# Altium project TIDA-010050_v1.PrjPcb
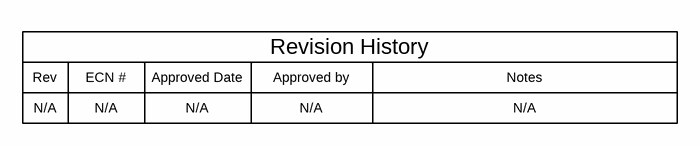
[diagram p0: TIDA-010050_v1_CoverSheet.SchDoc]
CopyrightYear: 2018; PCB_Layout: Aki Li; PCB_Rev: E1; PRJ_Customer: Public Release; PRJ_Engineer: Aki Li, Milen Stefanov; PRJ_Number: TIDA-010050; PRJ_Title: Ultra Low Power Flow Measurement Reference Design Using RF Wireless MCU; SCH_Rev: E1; TechSupport: http://www.ti.com/support; TID: TIDA-010050
3 sheets, 59 parts. Net scope: global (net labels, ports and power ports of the same name join across sheets).
Board file: TIDA-010050_v1.PcbDoc
Sheets:
  TIDA-010050_v1_CoverSheet.SchDoc
  TIDA-010050_v1_Hardware.SchDoc
  TIDA-010050_v1.SchDoc

## Sheet TIDA-010050_v1_CoverSheet.SchDoc
size 431 x 279 mm; Date: Not shown in title block; ApprovedBy: Not shown in title block; CheckedBy: Not shown in title block; Author: Not shown in title block; CompanyName: Not shown in title block; Engineer: Not shown in title block; Organization: Not shown in title block; Address1: Not shown in title block; Address2: Not shown in title block; Address3: Not shown in title block; Address4: Not shown in title block; DocumentNumber: 1; Revision: Use project parameter SCH_Rev; SheetNumber: 1; SheetTotal: 3; PageSetup: Record=PageOptions¦CenterHorizontal=True¦CenterVertical=True¦PrintScale=1.00¦XCorrection=1.00¦YCorrection=1.00¦PrintKind=0¦BorderSize=5000000¦LeftOffset=0¦BottomOffset=0¦Orientation=2¦PaperLength=1000¦PaperWidth=1000¦Scale=100¦PaperSource=15¦PrintQuality=600¦MediaType=1¦DitherType=10¦PaperKind=Letter¦PrintScaleMode=1

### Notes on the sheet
- Rev
- N/A
- ECN #
- Approved Date
- Approved by
- Revision History
- Notes

## Sheet TIDA-010050_v1_Hardware.SchDoc
size 431 x 279 mm; Date: Not shown in title block; ApprovedBy: Not shown in title block; CheckedBy: Not shown in title block; Author: Not shown in title block; CompanyName: Not shown in title block; Engineer: Not shown in title block; Organization: Not shown in title block; Address1: Not shown in title block; Address2: Not shown in title block; Address3: Not shown in title block; Address4: Not shown in title block; DocumentNumber: 3; Revision: Use project parameter SCH_Rev; SheetNumber: 3; SheetTotal: 3; PageSetup: Record=PageOptions¦CenterHorizontal=True¦CenterVertical=True¦PrintScale=1.00¦XCorrection=1.00¦YCorrection=1.00¦PrintKind=0¦BorderSize=5000000¦LeftOffset=0¦BottomOffset=0¦Orientation=2¦PaperLength=1000¦PaperWidth=1000¦Scale=100¦PaperSource=15¦PrintQuality=600¦MediaType=1¦DitherType=10¦PaperKind=Letter¦PrintScaleMode=1
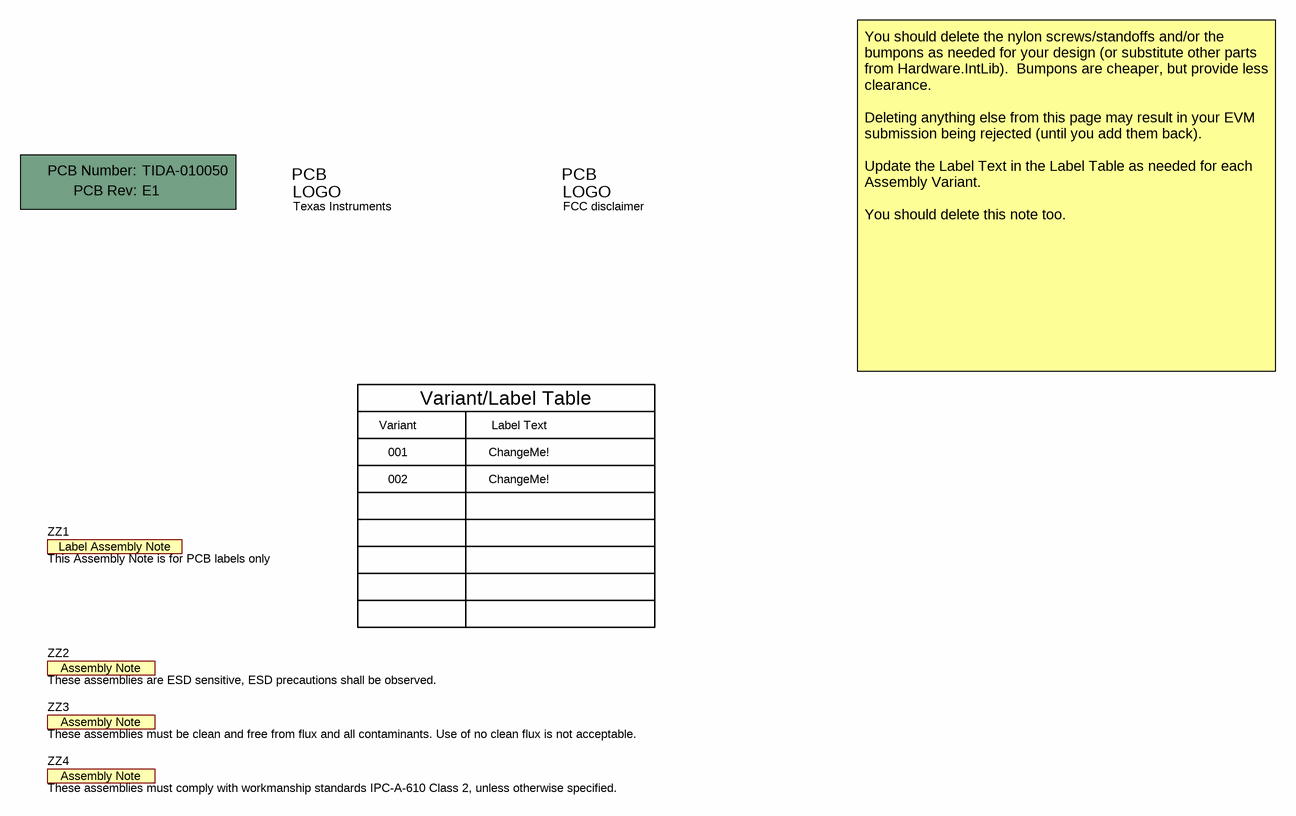
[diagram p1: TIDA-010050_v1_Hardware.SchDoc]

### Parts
!PCB  Printed Circuit Board  (value not drawn)  (mechanical)
Logo1  Texas Instruments  [TI_Stacked_Overlay_Small]  (no BOM)
Logo3  FCC disclaimer  [FCC_disclaimer]  (no BOM)
ZZ1  This Assembly Note is for PCB labels only  [AssemblyNoteLabel]  (no BOM)
ZZ2  These assemblies are ESD sensitive, ESD precautions shall be observed.  [AssemblyNote]  (no BOM)
ZZ3  These assemblies must be clean and free from flux and all contaminants. Use of no clean flux is not acceptable.  [AssemblyNote]  (no BOM)
ZZ4  These assemblies must comply with workmanship standards IPC-A-610 Class 2, unless otherwise specified.  [AssemblyNote]  (no BOM)

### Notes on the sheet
- Variant
- Variant/Label Table
- Label Text
- You should delete the nylon screws/standoffs and/or the bumpons as needed for your design (or substitute other parts from Hardware.IntLib).  Bumpons are cheaper, but provide less clearance.
  Deleting anything else from this page may result in your EVM submission being rejected (until you add them back).
  Update the Label Text in the Label Table as needed for each Assembly Variant.
  You should delete this note too.
- 001
- 002
- ChangeMe!

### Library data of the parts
!PCB = CMP-0003618-2: Manufacturer: Any; PartNumber: TIDA-010050
Logo1 = CMP-0074838-1: Texas Instrument Corporate Signature; SymbolCreator: a0412235; Lib Reference: TI_Logo; Library Reference: Logo
Logo3 = CMP-0074847-1: FCC_disclaimer; Library Reference: Logo
ZZ1 = CMP-0003616-3
ZZ2 = CMP-0077236-1
ZZ3 = CMP-0077237-1
ZZ4 = CMP-0077238-1

## Sheet TIDA-010050_v1.SchDoc
size 431 x 279 mm; Date: Not shown in title block; ApprovedBy: Not shown in title block; CheckedBy: Not shown in title block; Author: Not shown in title block; CompanyName: Not shown in title block; Engineer: Not shown in title block; Organization: Not shown in title block; Address1: Not shown in title block; Address2: Not shown in title block; Address3: Not shown in title block; Address4: Not shown in title block; DocumentNumber: 2; Revision: Use project parameter SCH_Rev; SheetNumber: 2; SheetTotal: 3; PageSetup: Record=PageOptions¦CenterHorizontal=True¦CenterVertical=True¦PrintScale=1.00¦XCorrection=1.00¦YCorrection=1.00¦PrintKind=0¦BorderSize=5000000¦LeftOffset=0¦BottomOffset=0¦Orientation=2¦PaperLength=1000¦PaperWidth=1000¦Scale=100¦PaperSource=15¦PrintQuality=600¦MediaType=1¦DitherType=10¦PaperKind=Letter¦PrintScaleMode=1
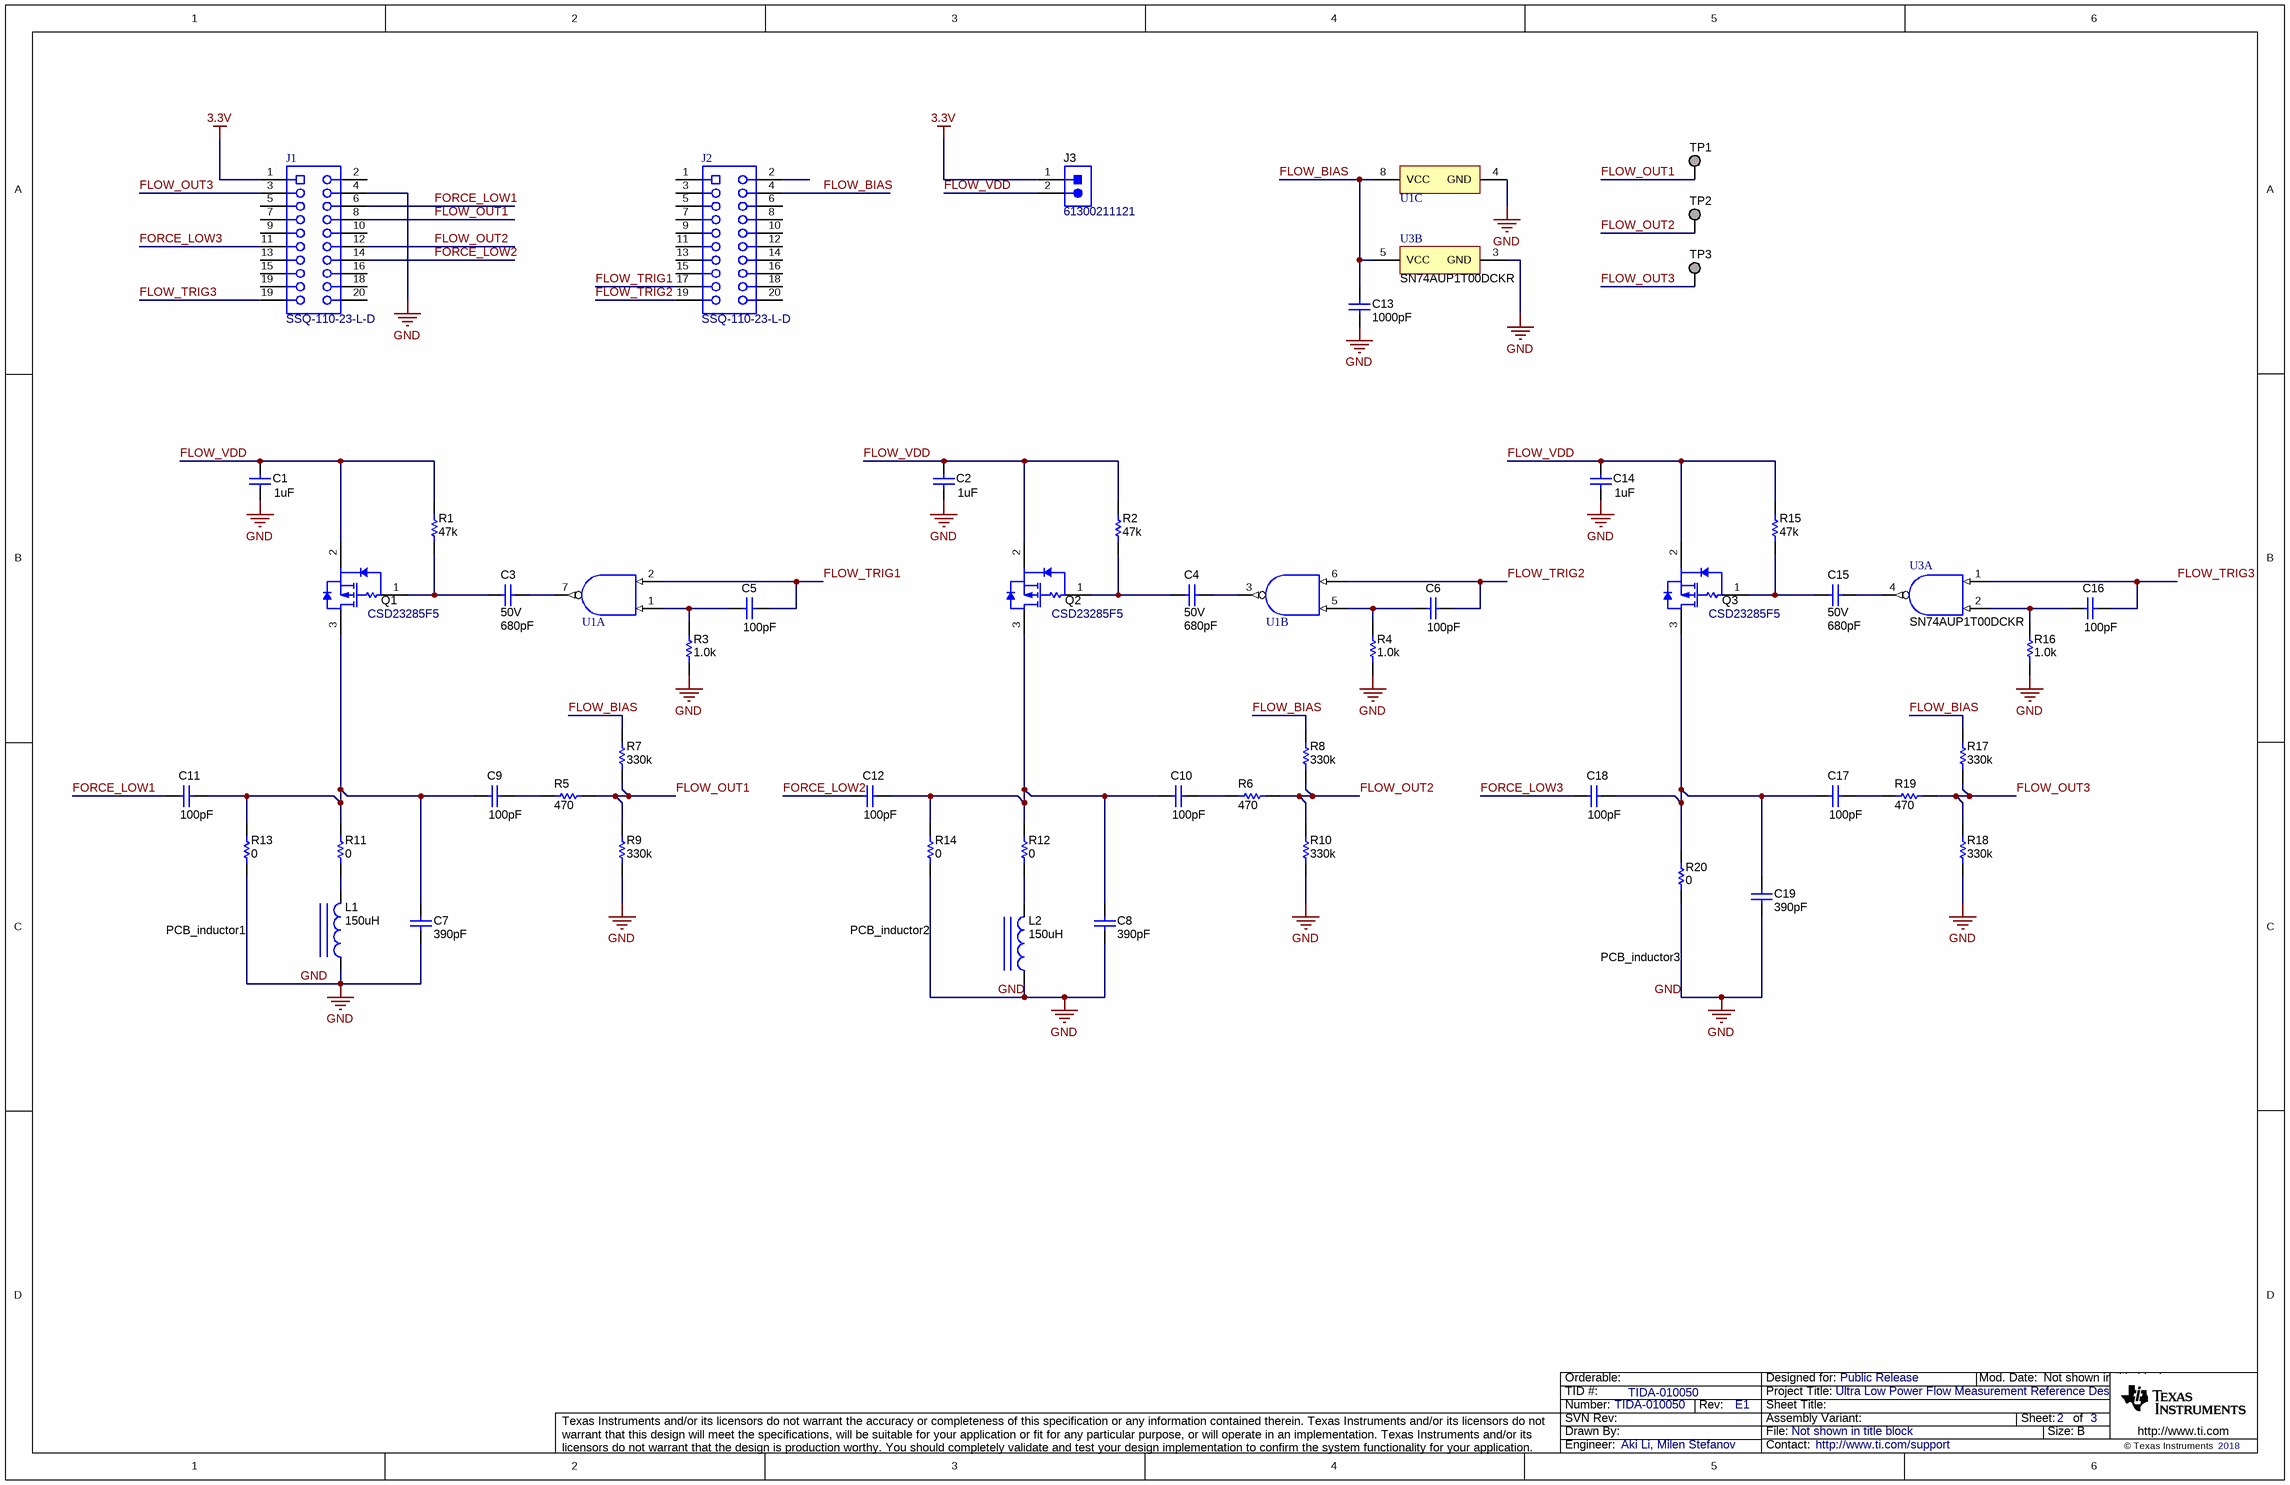
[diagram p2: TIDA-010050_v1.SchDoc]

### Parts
C1  ValueDisplayed: 1uF  [0402]  (hidden comment: GRM155C81A105KA12D)
C2  ValueDisplayed: 1uF  [0402]  (hidden comment: GRM155C81A105KA12D)
C3  VDC_V: 50V  ValueDisplayed: 680pF  [0402]  (hidden comment: GRM155R71H681KA01D)
C4  VDC_V: 50V  ValueDisplayed: 680pF  [0402]  (hidden comment: GRM155R71H681KA01D)
C5  ValueDisplayed: 100pF  [0402]  (hidden comment: GRM1555C1H101JA01D)
C6  ValueDisplayed: 100pF  [0402]  (hidden comment: GRM1555C1H101JA01D)
C7  ValueDisplayed: 390pF  [0402]  (hidden comment: GRM1555C1H391JA01D)
C8  ValueDisplayed: 390pF  [0402]  (hidden comment: GRM1555C1H391JA01D)
C9  ValueDisplayed: 100pF  [0402]  (hidden comment: GRM1555C1H101JA01D)
C10  ValueDisplayed: 100pF  [0402]  (hidden comment: GRM1555C1H101JA01D)
C11  ValueDisplayed: 100pF  [0402]  (hidden comment: GRM1555C1H101JA01D)
C12  ValueDisplayed: 100pF  [0402]  (hidden comment: GRM1555C1H101JA01D)
C13  ValueDisplayed: 1000pF  [0402]  (hidden comment: GRM155R61H102KA01D)
C14  ValueDisplayed: 1uF  [0402]  (hidden comment: GRM155C81A105KA12D)
C15  VDC_V: 50V  ValueDisplayed: 680pF  [0402]  (hidden comment: GRM155R71H681KA01D)
C16  ValueDisplayed: 100pF  [0402]  (hidden comment: GRM1555C1H101JA01D)
C17  ValueDisplayed: 100pF  [0402]  (hidden comment: GRM1555C1H101JA01D)
C18  ValueDisplayed: 100pF  [0402]  (hidden comment: GRM1555C1H101JA01D)
C19  ValueDisplayed: 390pF  [0402]  (hidden comment: GRM1555C1H391JA01D)
J1  SSQ-110-23-L-D  [Samtec_SSQ-110-23-x-D]
J2  SSQ-110-23-L-D  [Samtec_SSQ-110-23-x-D]
J3  61300211121  [WURTH_61300211121]
L1  ValueDisplayed: 150uH  [GT1128-0]  (hidden comment: GT1128-0)
L2  ValueDisplayed: 150uH  [GT1128-0]  (hidden comment: GT1128-0)
Q1  CSD23285F5  [YJK0003A]
Q2  CSD23285F5  [YJK0003A]
Q3  CSD23285F5  [YJK0003A]
R1  ValueDisplayed: 47k  [0402]  (hidden comment: CRCW040247K0JNED)
R2  ValueDisplayed: 47k  [0402]  (hidden comment: CRCW040247K0JNED)
R3  ValueDisplayed: 1.0k  [0402]  (hidden comment: CRCW04021K00JNED)
R4  ValueDisplayed: 1.0k  [0402]  (hidden comment: CRCW04021K00JNED)
R5  ValueDisplayed: 470  [0402]  (hidden comment: CRCW0402470RJNED)
R6  ValueDisplayed: 470  [0402]  (hidden comment: CRCW0402470RJNED)
R7  ValueDisplayed: 330k  [0402]  (hidden comment: CRCW0402330KJNED)
R8  ValueDisplayed: 330k  [0402]  (hidden comment: CRCW0402330KJNED)
R9  ValueDisplayed: 330k  [0402]  (hidden comment: CRCW0402330KJNED)
R10  ValueDisplayed: 330k  [0402]  (hidden comment: CRCW0402330KJNED)
R11  ValueDisplayed: 0  [0402]  (hidden comment: MCR01MZPJ000)
R12  ValueDisplayed: 0  [0402]  (hidden comment: MCR01MZPJ000)
R13  ValueDisplayed: 0  [0402]  (hidden comment: MCR01MZPJ000)
R14  ValueDisplayed: 0  [0402]  (hidden comment: MCR01MZPJ000)
R15  ValueDisplayed: 47k  [0402]  (hidden comment: CRCW040247K0JNED)
R16  ValueDisplayed: 1.0k  [0402]  (hidden comment: CRCW04021K00JNED)
R17  ValueDisplayed: 330k  [0402]  (hidden comment: CRCW0402330KJNED)
R18  ValueDisplayed: 330k  [0402]  (hidden comment: CRCW0402330KJNED)
R19  ValueDisplayed: 470  [0402]  (hidden comment: CRCW0402470RJNED)
R20  ValueDisplayed: 0  [0402]  (hidden comment: MCR01MZPJ000)
TP1  FLOW_OUT1  [TESTPOINT]  (value not drawn)  (no BOM)
TP2  FLOW_OUT2  [TESTPOINT]  (value not drawn)  (no BOM)
TP3  FLOW_OUT2  [TESTPOINT]  (value not drawn)  (no BOM)
U1  SN74AUP2G00DQER  [DQE0008A_V]  (value not drawn)  (parts A,B,C of 3)
U3  SN74AUP1T00DCKR  [DCK0005A_N]  (parts A,B of 2)

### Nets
3.3V: J1.1 J3.1
GND: C1.2 C2.2 C7.2 C8.2 C13.2 C14.2 C19.2 J1.4 L1.1 L2.1 R3.1 R4.1 R9.1 R10.1 R13.1 R14.1 R16.1 R18.1 R20.1 U1.4(GND) U3.3(GND)
FLOW_BIAS: C13.1 J2.4 R7.2 R8.2 R17.2 U1.8(VCC) U3.5(VCC)
FLOW_OUT1: J1.8 R5.2 R7.1 R9.2 TP1.1
FLOW_OUT2: J1.12 R6.2 R8.1 R10.2 TP2.1
FLOW_OUT3: J1.3 R17.1 R18.2 R19.2 TP3.1
FLOW_TRIG1: C5.1 J2.17 U1.2(1B)
FLOW_TRIG2: C6.1 J2.19 U1.6(2B)
FLOW_TRIG3: C16.1 J1.19 U3.1(A)
FLOW_VDD: C1.1 C2.1 C14.1 J3.2 Q1.2(S) Q2.2(S) Q3.2(S) R1.2 R2.2 R15.2
FORCE_LOW1: C11.2 J1.6
FORCE_LOW2: C12.2 J1.14
FORCE_LOW3: C18.2 J1.11
NetC3_1: C3.1 U1.7(1Y)
NetC3_2: C3.2 Q1.1(G) R1.1
NetC4_1: C4.1 U1.3(2Y)
NetC4_2: C4.2 Q2.1(G) R2.1
NetC5_2: C5.2 R3.2 U1.1(1A)
NetC6_2: C6.2 R4.2 U1.5(2A)
NetC7_1: C7.1 C9.2 C11.1 Q1.3(D) R11.2 R13.2
NetC8_1: C8.1 C10.2 C12.1 Q2.3(D) R12.2 R14.2
NetC9_1: C9.1 R5.1
NetC10_1: C10.1 R6.1
NetC15_1: C15.1 U3.4(Y)
NetC15_2: C15.2 Q3.1(G) R15.1
NetC16_2: C16.2 R16.2 U3.2(B)
NetC17_1: C17.1 R19.1
NetC17_2: C17.2 C18.1 C19.1 Q3.3(D) R20.2
NetL1_2: L1.2 R11.1
NetL2_2: L2.2 R12.1

Not connected (* = marked no-connect by the designer): J1 2 5 7 9 10 13 15 16 18 20; J2 1 2 3 5 6 7 8 9 10 11 12 13 14 15 16 18 20

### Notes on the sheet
- PCB_inductor1
- PCB_inductor2
- PCB_inductor3
- Labels drawn without touching a wire or pin: GND

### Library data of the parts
C1 C2 C14 = CMP-0064971-2: CAP, CERM, 1 uF, 10 V,+/- 10%, X6S, 0402; Manufacturer: MuRata; TaMin_C: -55°C; Polarized: N; SizeAreaWB_mm2: 3; Value1: Unknown; U/M: EA; Value: 1uF; TaMax_C: 105°C; SizeZ_mm: 0.6; SizeX_mm: 1; SizeY_mm: 0.5; Value2: 10V; Cap_F: 1µF; AEC Category: Q200
C3 C4 C15 = CMP-0006695-1: CAP, CERM, 680 pF, 50 V, +/- 10%, X7R, 0402; Manufacturer: MuRata; TaMin_C: -55°C; Polarized: N; SizeAreaWB_mm2: 3; Value1: Unknown; U/M: EA; Value: 680pF; TaMax_C: 125°C; SizeZ_mm: 0.6; SizeX_mm: 1; SizeY_mm: 0.5; AEC Category: Q200
C5 C6 C9-C12 C16-C18 = CMP-0006410-1: CAP, CERM, 100 pF, 50 V, +/- 5%, C0G/NP0, 0402; Manufacturer: MuRata; TaMin_C: -55°C; Polarized: N; SizeAreaWB_mm2: 3; Value1: Unknown; U/M: EA; Value: 100pF; TaMax_C: 125°C; SizeZ_mm: 0.6; SizeX_mm: 1; SizeY_mm: 0.5; Value2: 50V; AEC Category: Q200
C7 C8 C19 = CMP-0006459-2: CAP, CERM, 390 pF, 50 V, +/- 5%, C0G/NP0, 0402; Manufacturer: MuRata; TaMin_C: -55°C; Polarized: N; SizeAreaWB_mm2: 3; Value1: Unknown; U/M: EA; Value: 390pF; TaMax_C: 125°C; SizeZ_mm: 0.6; SizeX_mm: 1; SizeY_mm: 0.5; Value2: 50V; AEC Category: Q200
C13 = CMP-0006613-1: CAP, CERM, 1000 pF, 50 V, +/- 10%, X5R, 0402; Manufacturer: MuRata; TaMin_C: -55°C; Polarized: N; SizeAreaWB_mm2: 3; Value1: Unknown; U/M: EA; Value: 1000pF; TaMax_C: 85°C; SizeZ_mm: 0.6; SizeX_mm: 1; SizeY_mm: 0.5; Value2: 50V; Cap_F: 1nF; AEC Category: Q200
J1 J2 = CMP-0055702-1: Receptacle, 2.54mm, 10x2, Gold, TH; Manufacturer: Samtec; CNHeader: FALSE; Current_A: 6.3A; Gender: Female; Cert_CSA: Y; Voltage_V: 550V; CompType: Socket Strip; Row_Count: 2; RowSpacing_mm: 2.54; CT: TRUE
J3 = CMP-0054794-2: Header, 2.54 mm, 2x1, Gold, TH; Manufacturer: Wurth Elektronik; Shrouded: N; Gender: Male; Green_REACh: Passed; Pitch_mm: 2.54; Green_Lifecycle: Active; Row_Count: 1; Cert_UL: Y
L1 L2 = CMP-0062040-1: Inductor, 235uH, TH; Manufacturer: Gemphil Technologies; SizeAreaWB_mm2: 59.29; SizeZ_mm: 6.2; SizeX_mm: 5.7; Value2: A; SizeArea_mm2: 32.49; Ind_H: 235µH; AEC Qualified: N; AEC Category: Q200
Q1-Q3 = CMP-0000021-3: MOSFET, P-CH, -12 V, -3.3 A, YJK0003A (PICOSTAR-3); Alternate Manufacturer: None; Manufacturer: Texas Instruments; ChType: P; SizeY_mm: 0.73; IdsMax_A: -3.3A; ChMode: Enhancement; SizeZ_mm: 0.35; SizeAreaWB_mm2: 4.3077; Value: -12V; Value1: 0.03; AEC Qualified: N; QgTyp_nC: 3.2; AEC Category: Q101; SizeArea_mm2: 1.0877; SizeX_mm: 1.49; Rdson45_ohm: 0.035; Vgs_V: -6V; Value2: 3.2 nC
R1 R2 R15 = CMP-0026935-1: RES, 47 k, 5%, 0.063 W, 0402; Manufacturer: Vishay-Dale; Power_W: 63mW; TempCo: 200 ppm/C; Value_Code: 47k0; U/M: EA; Value: 47k; EIA_Code: E24; SizeX_mm: 1; SizeY_mm: 0.5; SizeZ_mm: 0.6; Value2: 0.063W; VDC_V: 50V; AEC Category: Q200
R3 R4 R16 = CMP-0026852-1: RES, 1.0 k, 5%, 0.063 W, 0402; Manufacturer: Vishay-Dale; Power_W: 63mW; TempCo: 200 ppm/C; Value_Code: 1k00; U/M: EA; Value: 1.0k; EIA_Code: E24; Res_ohm: 1k; SizeX_mm: 1; SizeY_mm: 0.5; SizeZ_mm: 0.6; Value2: 0.063W; VDC_V: 50V; AEC Category: Q200
R5 R6 R19 = CMP-0026934-1: RES, 470, 5%, 0.063 W, 0402; Manufacturer: Vishay-Dale; Power_W: 63mW; TempCo: 200 ppm/C; Value_Code: 470R; U/M: EA; Value: 470; EIA_Code: E24; SizeX_mm: 1; SizeY_mm: 0.5; SizeZ_mm: 0.6; Value2: 0.063W; VDC_V: 50V; AEC Category: Q200
R7-R10 R17 R18 = CMP-0026905-1: RES, 330 k, 5%, 0.063 W, 0402; Manufacturer: Vishay-Dale; Power_W: 63mW; TempCo: 200 ppm/C; U/M: EA; Value: 330k; EIA_Code: E24; SizeX_mm: 1; SizeY_mm: 0.5; SizeZ_mm: 0.6; Value2: 0.063W; VDC_V: 50V; AEC Category: Q200
R11-R14 R20 = CMP-0027002-2: RES, 0, 5%, 0.063 W, 0402; Manufacturer: Rohm; Power_W: 63mW; TempCo: 500 ppm/C; Value_Code: 0000; U/M: EA; Value: 0; EIA_Code: E24; SizeX_mm: 1; SizeY_mm: 0.5; SizeZ_mm: 0.6; Value2: 0.063W; VDC_V: 50V; AEC Category: Q200
TP1-TP3 = CMP-0078143-2: TEST POINT.  No entry in BOM.
U1 = CMP-0051930-1: Low-Power Dual 2-Input Positive-NAND Gate, DQE0008A, LARGE T&R; Manufacturer: Texas Instruments; Output Drive (IOL/IOH)(Max)(mA): 20/-20; F @ Nom Voltage(Max)(Mhz): 100; 3-State Output: No; Technology Family: AUP; Bits(#): 2; Rating: Catalog; Voltage(Nom)(V): 0.8,1.2,1.5,1.8,2.5,3.3; tpd @ Nom Voltage(Max)(ns): 31.8,26.3,16.6,12.9,8.8,6.7; VCC(Min)(V): 0.8; ICC @ Nom Voltage(Max)(mA): 0.0009; Logic: True; Input Type: CMOS; VCC(Max)(V): 3.6; Gate Type: NAND
U3 = CMP-0051743-2: Low Power, 1.8/2.5/3.3-V In, 3.3-V CMOS Out, Single 2-Input Positive-NAND Gate, DCK0005A, LARGE T&R; Manufacturer: Texas Instruments; Schmitt Trigger: No; tpd @ Nom Voltage(Max)(ns): 9.8,8.5,7.8; Output Drive (IOL/IOH)(Max)(mA): 4/-4; ICC @ Nom Voltage(Max)(mA): 0.0009; VCC(Min)(V): 0.8; VCC(Max)(V): 3.6; Sub-Family: Single Supply Translator; Rating: Catalog; Voltage(Nom)(V): 1.8,2.5,3.3; Bits(#): 1; Technology Family: AUP1T; F @ Nom Voltage(Max)(Mhz): 190; Logic: True; AEC Category: Q200; AEC Qualified: N; CompType: IC; SizeAreaWB_mm2: 9.3; SizeArea_mm2: 4.2; SizeX_mm: 2.1; SizeY_mm: 2.0; SizeZ_mm: 1.1

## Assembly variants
001: not fitted R13 R14 R20 R21 R22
